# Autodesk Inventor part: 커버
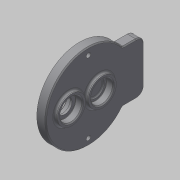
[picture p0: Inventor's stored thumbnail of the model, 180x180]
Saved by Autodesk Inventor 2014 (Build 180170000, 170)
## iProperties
Created: 2016-02
Part Number: 커버
Material: 일반
Document SubType Name: Modeling
Designer: mduedu
Density: 1 g/cm^3
Appearance: 기본값
Author: mduedu
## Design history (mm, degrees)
sketch "스케치1"
  geometry: C1 r 43 at (0, 0); 1 further point
  constraints: 1 centre point, 1 coincident
  dimensions: "d0" = 86 diameter of C1
extrude "돌출1" new body sketch "스케치1" distance "d1" = 9; taper "d2" = 0 deg
sketch "스케치2"
  geometry: C1 r 14 at (0, 11); 1 further point
  constraints: 1 centre point, 1 vertical alignment
  dimensions: "d3" = 28 diameter of C1; "d6" = 11 distance of C1.centre point (0, 0)
extrude "돌출2" join sketch "스케치2" distance "d7" = 3; taper "d8" = 0 deg
sketch "스케치3"
  geometry: C1 r 14 at (0, -20); 1 further point
  constraints: 1 centre point, 1 vertical alignment
  dimensions: "d9" = 28 diameter of C1; "d10" = 20 distance of C1.centre point (0, 0)
extrude "돌출3" join sketch "스케치3" distance "d11" = 3; taper "d12" = 0 deg
hole "구멍1" diameter "d15" = 22; stored, may be unused: countersink angle "d19" = 90 deg, drill point angle "d21" = 0 deg; dims "d13" = 10, "d14" = 10, "d16" = 6, "d17" = 4, "d18" = 2, "d20" = 7
hole "구멍2" diameter "d24" = 18; stored, may be unused: countersink angle "d28" = 90 deg, drill point angle "d30" = 0 deg; dims "d22" = 10, "d23" = 10, "d25" = 6, "d26" = 4, "d27" = 2, "d29" = 1
hole "구멍3" diameter "d33" = 22; stored, may be unused: countersink angle "d37" = 90 deg, drill point angle "d39" = 0 deg; dims "d34" = 6, "d35" = 4, "d36" = 2, "d38" = 7, "d73" = 10, "d74" = 10
sketch "스케치7"
  geometry: L1 (-26, 34.249)-(26, 34.249); L2 (26, 34.249)-(26, 56); L3 (26, 56)-(-26, 56); L4 (-26, 56)-(-26, 34.249); A1 r 43 centre (0, 0) between (-26, 34.249) and (26, 34.249) reference; 1 further point
  constraints: 8 end point, 2 parallel, 2 point on circle, 1 horizontal, 1 perpendicular
  dimensions: "d95" = 52 distance of L2.end L3.end; "d97" = 56 distance from line of L3 point (0, 0)
extrude "돌출5" join sketch "스케치7" stored distance "d98" = 10; taper "d99" = 0 deg
sketch "스케치4"
  geometry: C1 r 14 at (0, -20) reference; C2 r 18 at (0, -20); 1 further point
  constraints: 1 centre point, 1 coincident
  dimensions: "d40" = 36 diameter of C2
extrude "돌출4" join sketch "스케치4" distance "d41" = 4; taper "d42" = 0 deg
hole "구멍4" diameter "d45" = 22; stored, may be unused: countersink angle "d49" = 90 deg, drill point angle "d51" = 0 deg; dims "d43" = 10, "d44" = 10, "d46" = 6, "d47" = 4, "d48" = 2, "d50" = 7
hole "구멍5" diameter "d54" = 15; stored, may be unused: countersink angle "d58" = 90 deg, drill point angle "d60" = 0 deg; dims "d52" = 10, "d53" = 10, "d55" = 6, "d56" = 4, "d57" = 2, "d59" = 7
fillet "모깎기1" dims "d61" = 0.3
fillet "모깎기2" dims "d62" = 2
chamfer "모따기1" distance "d63" = 1; stored, may be unused: second distance "d64" = 2, angle "d65" = 45 deg
fillet "모깎기6" dims "d88" = 2
sketch "스케치5" dims "d67" = 72
  geometry: 4 further points
  constraints: 2 horizontal alignment, 1 coincident, 5 other
  dimensions: "d71" = 360 deg dimension on point (0, 0) point (-36, 0) (derived)
fillet "모깎기4" dims "d75" = 2
sketch "스케치6"
  geometry: 2 further points
hole "구멍6" sketch "스케치6" at (36, 0), (-36, 0) diameter "d76" = 4.5; stored, may be unused: countersink angle "d80" = 90 deg, drill point angle "d82" = 0 deg; dims "d77" = 6, "d78" = 8, "d79" = 4.6, "d81" = 8
fillet "모깎기7" dims "d100" = 8, "d101" = 2
chamfer "모따기2" distance "d90" = 1; stored, may be unused: second distance "d91" = 2, angle "d92" = 45 deg
node "솔리드1"
node "절단 모서리 투영1"
